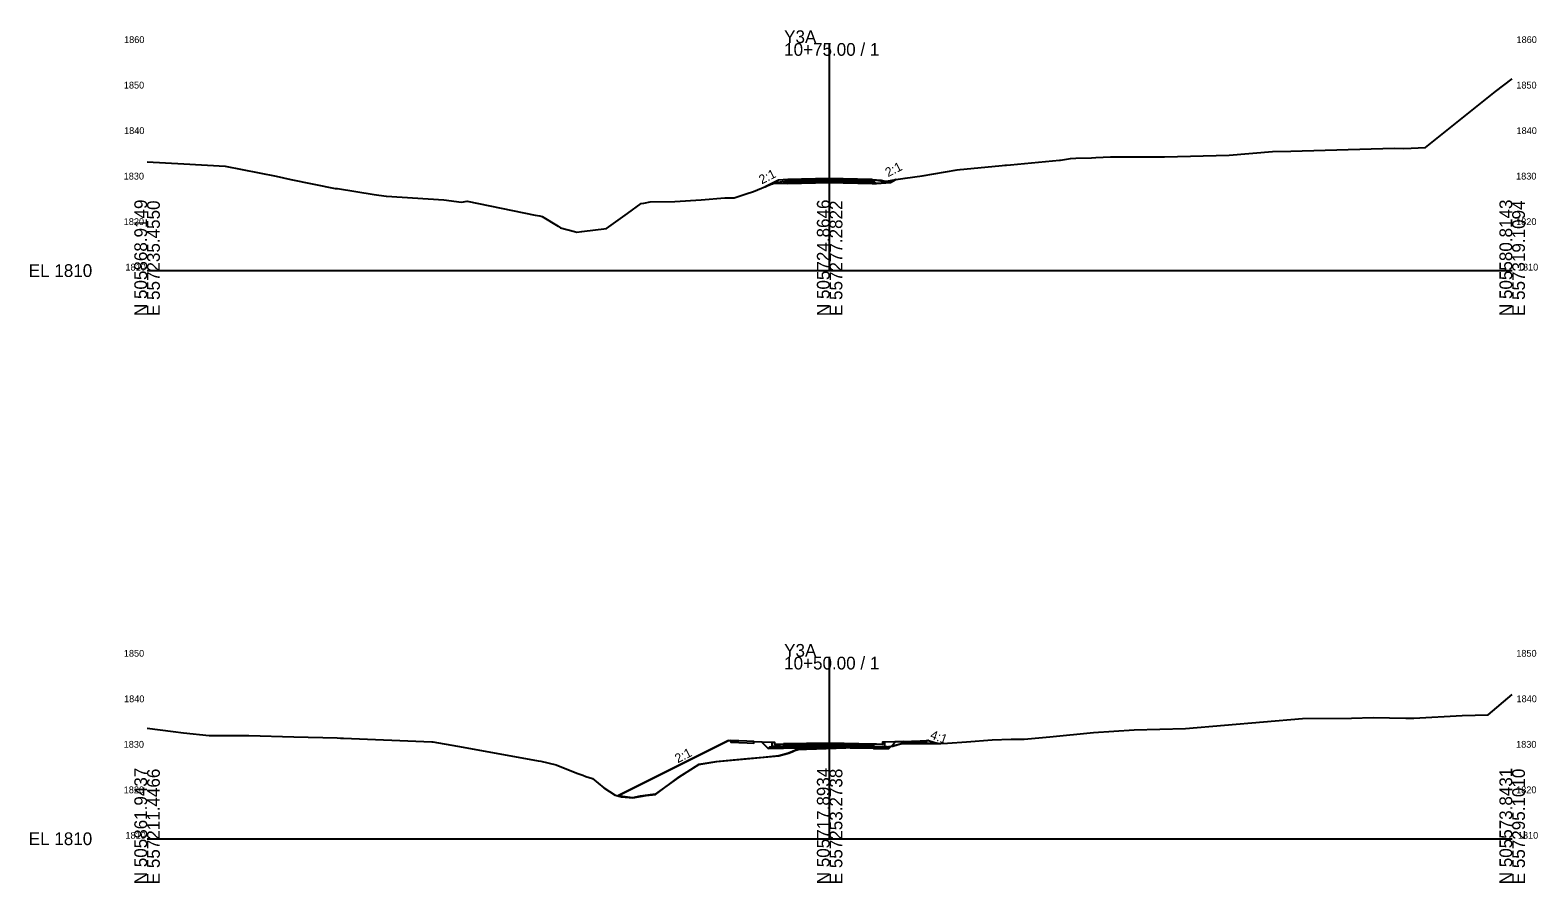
# Model space of a CAD drawing. Extents: x -26 to 306, y -102 to 258.
# Drawn here: x -25.7 to 305.6, y 70.3 to 257.7 of the extents above; entities that cross this region are included whole.
import ezdxf

# ---------------------------------------------------------------- set-up
doc = ezdxf.new("R2010")
doc.units = 0
for name, color, linetype in [('Default', 7, 'Continuous'), ('Exist Cross Section Cell', 7, 'Continuous'), ('Exist XS Ground Line', 7, 'Continuous'), ('Prop CMT Pvmt Course 1', 7, 'Continuous'), ('Prop CMT Pvmt Course 2', 7, 'Continuous'), ('Prop CMT Pvmt Course 3', 7, 'Continuous'), ('Prop CMT Pvmt Course 4', 7, 'Continuous'), ('Prop CMT Shld Paved Course 1', 7, 'Continuous'), ('Prop CMT Shld Paved Course 2', 7, 'Continuous'), ('Prop CMT Shld Paved Course 3', 7, 'Continuous'), ('Prop CMT Subgrade Earthwork', 7, 'Continuous'), ('Prop Conc 4in Sidewalk', 7, 'Continuous'), ('Prop Conc Curb and Gutter', 7, 'Continuous'), ('Prop Corridor Mesh Bottom', 7, 'Continuous'), ('Prop XS Elevation Labels', 7, 'Continuous'), ('Prop XS Finish Grade', 7, 'Continuous'), ('Prop XS Label Text', 7, 'Continuous'), ('Scratch_Level_1', 7, 'Continuous'), ('Scratch_Level_9', 7, 'Continuous')]:
    doc.layers.add(name, color=color, linetype=linetype)

msp = doc.modelspace()

# ---------------------------------------------------------------- linework, layer by layer
at = {"layer": 'Exist Cross Section Cell'}
for p, q in [((150, 204.87), (150, 254.87)), ((0, 204.87), (150, 204.87)), ((150, 204.87), (300, 204.87)), ((150, 80), (150, 120)), ((0, 80), (150, 80)), ((150, 80), (300, 80))]:
    msp.add_line(p, q, dxfattribs=at)
at = {"layer": 'Exist XS Ground Line'}
for points in [[(0, 228.79), (8.07, 228.32), (17.13, 227.83), (28.34, 225.64), (31.56, 224.91), (41.31, 222.94), (41.84, 222.87), (49.89, 221.61), (52.54, 221.2), (52.64, 221.19), (65.2, 220.44), (69.11, 219.88), (70.35, 220.1), (85.27, 217.08), (86.3, 216.87), (86.79, 216.73), (90.34, 214.61), (90.88, 214.29), (93.96, 213.43), (94.48, 213.31), (95.55, 213.47), (100.94, 214.1), (105.61, 217.39), (108.61, 219.64), (109.16, 219.68), (110.58, 219.95), (115.99, 220.05), (121.8, 220.39), (126.97, 220.85), (128.99, 220.87), (131.69, 221.71), (133.24, 222.22), (137.18, 223.83), (138.1, 224.2), (140.63, 224.6), (140.64, 224.64), (147.48, 224.87), (149.7, 224.97), (152.11, 224.99), (157.61, 224.91), (159.29, 224.91), (159.43, 224.87), (162.11, 224.46), (164.58, 224.87), (166.58, 225.18), (170.37, 225.71), (175.43, 226.56), (178.05, 226.98), (178.65, 227.09), (187.16, 227.92), (187.9, 227.99), (188.5, 228.02), (188.9, 228.06), (189.77, 228.12), (200.51, 229.12), (200.73, 229.16), (202.93, 229.47), (204.14, 229.54), (207.56, 229.66), (208.48, 229.71), (211.71, 229.85), (223.56, 229.84), (237.78, 230.26), (247.3, 231.06), (251.33, 231.1), (274.05, 231.75), (276.22, 231.7), (280.98, 231.92), (296.31, 244.19), (300, 247.04)], [(0, 104.31), (5.74, 103.55), (8, 103.27), (13.63, 102.69), (21.23, 102.72), (22.33, 102.71), (32.24, 102.39), (41.79, 102.16), (42.48, 102.14), (43.14, 102.13), (62.61, 101.3), (62.78, 101.29), (68.21, 100.37), (69.5, 100.16), (72.28, 99.62), (83.16, 97.62), (85.95, 97.12), (86.52, 97.02), (89.92, 96.22), (94.46, 94.42), (95.74, 93.95), (96.4, 93.69), (97.91, 93.27), (100.36, 91.17), (102.9, 89.57), (104.28, 89.24), (106.76, 89.02), (109.69, 89.5), (111.71, 89.73), (116.94, 93.62), (121.23, 96.3), (125.21, 96.98), (129.25, 97.35), (138.82, 98.21), (141.01, 98.79), (141.78, 99.12), (142.38, 99.39), (143.11, 99.65), (144.94, 99.67), (151.47, 99.9), (157.7, 100.16), (160.6, 100.18), (161.54, 100.06), (161.97, 100.05), (162.89, 100.19), (163.85, 100.33), (163.88, 100.34), (164.85, 100.64), (166.03, 100.94), (174.45, 100.95), (175.88, 101.02), (180.06, 101.27), (185.74, 101.73), (189.9, 101.85), (192.76, 101.92), (198.39, 102.41), (207.99, 103.36), (216.95, 103.92), (228.24, 104.25), (253.88, 106.4), (264.72, 106.52), (269.41, 106.65), (276.65, 106.48), (278.35, 106.5), (289.04, 107.07), (294.72, 107.22), (300, 111.72)]]:
    msp.add_lwpolyline(points, dxfattribs=at)
at = {"layer": 'Prop CMT Pvmt Course 1'}
for points in [[(140.79, 224.75), (140.79, 224.67), (143.85, 224.73), (150, 224.86), (152.99, 224.8), (159.34, 224.67), (159.34, 224.75), (159.34, 224.92), (152.99, 225.05), (150, 225.11), (143.85, 224.98), (140.79, 224.92), (140.79, 224.75)], [(139.88, 100.86), (139.88, 100.61), (150, 100.79), (150, 100.79), (150, 100.79), (150, 100.79), (159.63, 100.57), (159.63, 100.82), (150, 101.04), (150, 101.04), (150, 101.04), (150, 101.04), (139.88, 100.86)]]:
    msp.add_lwpolyline(points, dxfattribs=at)
at = {"layer": 'Prop CMT Pvmt Course 2'}
for points in [[(140.79, 224.45), (140.79, 224.34), (143.85, 224.4), (150, 224.52), (152.99, 224.46), (159.34, 224.34), (159.34, 224.44), (159.34, 224.67), (152.99, 224.8), (150, 224.86), (143.85, 224.73), (140.79, 224.67), (140.79, 224.45)], [(139.88, 100.61), (139.88, 100.27), (150, 100.46), (150, 100.46), (150, 100.46), (150, 100.46), (159.63, 100.24), (159.63, 100.57), (150, 100.79), (150, 100.79), (150, 100.79), (150, 100.79), (139.88, 100.61)]]:
    msp.add_lwpolyline(points, dxfattribs=at)
at = {"layer": 'Prop CMT Pvmt Course 3'}
for points in [[(140.79, 224.11), (140.79, 224), (143.85, 224.07), (150, 224.19), (152.99, 224.13), (159.34, 224), (159.34, 224.11), (159.34, 224.34), (152.99, 224.46), (150, 224.52), (143.85, 224.4), (140.79, 224.34), (140.79, 224.11)], [(138.75, 100.26), (139.88, 100.27), (139.88, 100.16), (139.88, 99.9), (138.56, 99.89), (136.49, 99.86), (136.7, 100.07), (136.87, 100.23), (138.75, 100.26)], [(139.88, 100.27), (139.88, 99.94), (150, 100.12), (150, 100.12), (150, 100.12), (150, 100.12), (159.63, 99.9), (159.63, 100.24), (150, 100.46), (150, 100.46), (150, 100.46), (150, 100.46), (139.88, 100.27)], [(160.76, 100.23), (159.63, 100.24), (159.63, 100.13), (159.63, 99.86), (160.95, 99.85), (163.02, 99.83), (162.81, 100.04), (162.64, 100.2), (160.76, 100.23)]]:
    msp.add_lwpolyline(points, dxfattribs=at)
at = {"layer": 'Prop CMT Pvmt Course 4'}
msp.add_lwpolyline([(139.88, 99.94), (150, 100.12), (150, 100.12), (150, 100.12), (150, 100.12), (159.63, 99.9)], dxfattribs=at)
at = {"layer": 'Prop CMT Shld Paved Course 1'}
for points in [[(140.79, 224.92), (140.79, 224.67), (140.54, 224.67), (140.79, 224.92), (140.79, 224.92)], [(159.34, 224.92), (159.34, 224.67), (159.6, 224.66), (159.34, 224.92), (159.34, 224.92)]]:
    msp.add_lwpolyline(points, dxfattribs=at)
at = {"layer": 'Prop CMT Shld Paved Course 2'}
for points in [[(140.79, 224.67), (140.79, 224.34), (140.2, 224.33), (140.54, 224.67), (140.79, 224.67)], [(159.34, 224.67), (159.34, 224.34), (159.94, 224.32), (159.6, 224.66), (159.34, 224.67)]]:
    msp.add_lwpolyline(points, dxfattribs=at)
at = {"layer": 'Prop CMT Shld Paved Course 3'}
for points in [[(140.79, 224.34), (140.79, 224), (139.86, 223.99), (140.2, 224.33), (140.79, 224.34)], [(159.34, 224.34), (159.34, 224), (160.28, 223.98), (159.94, 224.32), (159.34, 224.34)]]:
    msp.add_lwpolyline(points, dxfattribs=at)
at = {"layer": 'Prop CMT Subgrade Earthwork'}
msp.add_line((160.28, 223.98), (163.34, 224.26), dxfattribs=at)
for points in [[(139.86, 223.99), (137.14, 223.93)], [(135.04, 101.32), (135.71, 100.64), (136.49, 99.86), (138.56, 99.89), (139.88, 99.9)], [(164.47, 101.29), (163.8, 100.6), (163.02, 99.83), (160.95, 99.85), (159.63, 99.86)]]:
    msp.add_lwpolyline(points, dxfattribs=at)
at = {"layer": 'Prop Conc 4in Sidewalk'}
for points in [[(128.92, 101.54), (128.28, 101.58), (128.28, 101.48), (128.27, 101.25), (128.91, 101.21), (130.08, 101.16), (131.85, 101.08), (133.36, 101.04), (133.36, 101.16), (133.35, 101.37), (131.84, 101.41), (130.08, 101.5), (128.92, 101.54)], [(170.59, 101.51), (171.23, 101.55), (171.23, 101.45), (171.24, 101.22), (170.6, 101.17), (169.43, 101.13), (167.67, 101.04), (166.15, 101.01), (166.15, 101.12), (166.16, 101.34), (167.67, 101.38), (169.43, 101.46), (170.59, 101.51)]]:
    msp.add_lwpolyline(points, dxfattribs=at)
at = {"layer": 'Prop Conc Curb and Gutter'}
for points in [[(139.19, 100.82), (139.88, 100.86), (139.88, 100.68), (139.88, 100.27), (138.98, 100.27), (137.37, 100.24), (137.37, 100.85), (137.37, 101.25), (137.56, 101.25), (137.87, 101.25), (137.87, 101.06), (137.87, 100.75), (139.19, 100.82)], [(160.32, 100.79), (159.63, 100.82), (159.63, 100.65), (159.63, 100.24), (160.53, 100.23), (162.14, 100.2), (162.14, 100.81), (162.14, 101.22), (161.95, 101.22), (161.64, 101.21), (161.64, 101.03), (161.64, 100.71), (160.32, 100.79)]]:
    msp.add_lwpolyline(points, dxfattribs=at)
at = {"layer": 'Prop Corridor Mesh Bottom'}
for points in [[(159.34, 224.92), (159.34, 224.67)], [(159.63, 100.82), (159.63, 100.57)]]:
    msp.add_lwpolyline(points, dxfattribs=at)
at = {"layer": 'Prop XS Finish Grade'}
for p, q in [((127.77, 101.61), (103.43, 89.44)), ((171.74, 101.58), (173.86, 100.95))]:
    msp.add_line(p, q, dxfattribs=at)
for points in [[(138.79, 224.76), (135.84, 223.28)], [(140.79, 224.92), (138.79, 224.76)], [(159.34, 224.92), (161.34, 224.76)], [(161.34, 224.76), (163.34, 224.26), (163.34, 224.26), (163.34, 224.26), (164.52, 224.85)], [(127.77, 101.61), (127.95, 101.6), (128.28, 101.58)], [(133.35, 101.37), (135.18, 101.31), (137.37, 101.25)], [(139.88, 100.86), (150, 101.04), (159.63, 100.82)], [(166.16, 101.34), (164.33, 101.27), (162.14, 101.22)], [(171.74, 101.58), (171.56, 101.56), (171.23, 101.55)]]:
    msp.add_lwpolyline(points, dxfattribs=at)
at = {"layer": 'Scratch_Level_1'}
for points in [[(135.84, 223.28), (137.14, 223.93), (137.42, 223.94)], [(138.1, 224.2), (140.63, 224.6), (140.64, 224.64), (143.85, 224.73), (147.48, 224.87), (149.7, 224.97), (152.11, 224.99), (157.61, 224.91), (159.34, 224.92), (162.11, 224.46), (162.41, 224.52), (163.01, 224.58), (164.58, 224.87), (163.34, 224.26), (160.28, 223.98), (159.34, 224), (150, 224.19), (140.79, 224), (139.86, 223.99), (137.43, 223.94)], [(103.43, 89.44), (127.77, 101.61), (128.28, 101.58), (128.27, 101.25), (131.85, 101.08), (133.36, 101.04), (133.35, 101.37), (135.04, 101.32), (136.49, 99.86), (139.88, 99.9), (150, 100.12), (154.27, 100.04), (150.18, 99.86), (145.95, 99.72), (144.49, 99.68), (143.31, 99.63), (142.88, 99.61), (142.37, 99.39), (140.97, 98.82), (138.82, 98.23), (135.4, 97.88), (131.96, 97.58), (127.25, 97.15), (125.01, 96.93), (121.25, 96.32), (116.82, 93.48), (111.66, 89.78), (108.35, 89.35), (106.71, 88.96)], [(163.43, 100.26), (161.97, 100.05), (161.54, 100.06), (160.6, 100.18), (159.43, 100.17), (157.7, 100.16), (154.49, 100.01), (159.63, 99.9), (159.63, 99.86), (163.02, 99.83)], [(164.47, 101.29), (166.16, 101.34), (171.74, 101.58), (173.86, 100.95), (171.49, 100.95), (169.08, 100.94), (166.03, 100.94), (163.88, 100.34), (163.49, 100.28)]]:
    msp.add_lwpolyline(points, close=True, dxfattribs=at)
at = {"layer": 'Scratch_Level_9'}
for points in [[(140.79, 224.92), (140.79, 224.67)], [(139.88, 100.86), (139.88, 100.61)], [(159.63, 100.82), (159.63, 100.57)]]:
    msp.add_lwpolyline(points, dxfattribs=at)

# ---------------------------------------------------------------- texts
at = {"layer": 'Default'}
for p in [(0, 204.87), (0, 80)]:
    msp.add_text('-', height=0.0001, dxfattribs=at).set_placement(p)
at = {"layer": 'Exist Cross Section Cell'}
for s, p in [('Y3A', (140, 254.87)), ('10+75.00 / 1', (140, 252.07)), ('EL 1810', (-26, 203.47)), ('Y3A', (140, 120)), ('10+50.00 / 1', (140, 117.2)), ('EL 1810', (-26, 78.6))]:
    msp.add_text(s, height=2.8, dxfattribs=at).set_placement(p)
for s, p in [('N 505868.9149', (0, 194.87)), ('E 557235.4550', (2.8, 194.87)), ('N 505724.8646', (150, 194.87)), ('E 557277.2822', (152.8, 194.87)), ('N 505580.8143', (300, 194.87)), ('E 557319.1094', (302.8, 194.87)), ('N 505861.9437', (0, 70)), ('E 557211.4466', (2.8, 70)), ('N 505717.8934', (150, 70)), ('E 557253.2738', (152.8, 70)), ('N 505573.8431', (300, 70)), ('E 557295.1010', (302.8, 70))]:
    msp.add_text(s, height=2.8, rotation=90, dxfattribs=at).set_placement(p)
at = {"layer": 'Prop XS Elevation Labels'}
for s, p in [('1860', (-5.05, 254.87)), ('1860', (300.95, 254.87)), ('1850', (-5.1, 244.87)), ('1850', (300.9, 244.87)), ('1840', (-5.05, 234.87)), ('1840', (300.95, 234.87)), ('1830', (-5.14, 224.87)), ('1830', (300.86, 224.87)), ('1820', (-5.13, 214.87)), ('1820', (300.87, 214.87)), ('1810', (-4.75, 204.87)), ('1810', (301.25, 204.87)), ('1850', (-5.1, 120)), ('1850', (300.9, 120)), ('1840', (-5.05, 110)), ('1840', (300.95, 110)), ('1830', (-5.14, 100)), ('1830', (300.86, 100)), ('1820', (-5.13, 90)), ('1820', (300.87, 90)), ('1810', (-4.75, 80)), ('1810', (301.25, 80))]:
    msp.add_text(s, height=1.5, dxfattribs=at).set_placement(p)
at = {"layer": 'Prop XS Finish Grade'}
for p in [(134.97, 222.85), (140.79, 224.92), (150, 225.1), (159.34, 224.92), (159.34, 224.92), (163.34, 224.26), (164.52, 224.85), (128.28, 101.58), (133.35, 101.37), (137.87, 100.75), (139.88, 100.85), (159.63, 100.82), (159.63, 100.82), (163.63, 100.16), (164.25, 100.47)]:
    msp.add_text('X', height=0.0025, dxfattribs=at).set_placement(p)
for p in [(159.63, 100.82), (161.64, 100.71), (166.16, 101.34), (171.23, 101.55)]:
    msp.add_text('X', height=0.0025, rotation=360, dxfattribs=at).set_placement(p)
at = {"layer": 'Prop XS Label Text'}
for s, rotation, p in [('2:1', 26.8657, (135.08, 223.8)), ('2:1', 26.8657, (162.83, 225.38)), ('4:1', 340.3273, (171.94, 102.06)), ('2:1', 26.8657, (116.61, 96.58))]:
    msp.add_text(s, height=2, rotation=rotation, dxfattribs=at).set_placement(p)

doc.saveas('drawing.dxf')
